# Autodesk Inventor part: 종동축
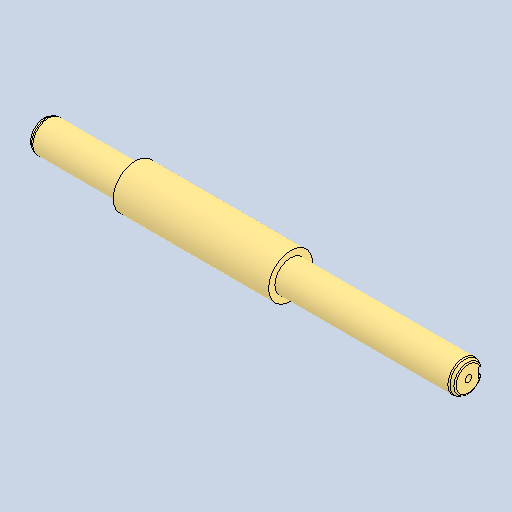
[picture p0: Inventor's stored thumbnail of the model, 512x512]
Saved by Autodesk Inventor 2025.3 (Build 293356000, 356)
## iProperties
Created: 2026-01
Part Number: 종동축
Material: 강철, 탄소
Document SubType Name: Modeling
Designer: pc6
Density: 7.85 g/cm^3
Appearance: 기본값
Author: jhkim
Sending System: Autodesk Inventor 2026
Preprocessor: ST-DEVELOPER v20.1
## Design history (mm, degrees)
feature "솔리드1"
node "솔리드2"
